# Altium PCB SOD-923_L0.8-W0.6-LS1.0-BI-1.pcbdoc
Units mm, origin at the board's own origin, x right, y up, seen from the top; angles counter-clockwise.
Board outline 14.1 x 13.46 mm, 2 copper layers (Top Layer, Bottom Layer), stack 0 mm thick; 1 components, 0 nets, 2 pads, 0 vias.
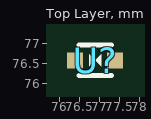
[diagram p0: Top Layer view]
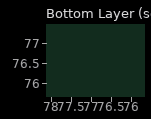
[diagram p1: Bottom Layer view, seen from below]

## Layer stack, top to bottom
Top Layer: signal copper (thickness not stored)
Bottom Layer: signal copper (thickness not stored)

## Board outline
83.95,69.85 69.85,69.85 69.85,83.312 83.95,83.312

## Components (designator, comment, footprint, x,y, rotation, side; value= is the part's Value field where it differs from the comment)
U? "" SOD-923_L0.8-W0.6-LS1.0-BI-1 76.9,76.581 r0 top

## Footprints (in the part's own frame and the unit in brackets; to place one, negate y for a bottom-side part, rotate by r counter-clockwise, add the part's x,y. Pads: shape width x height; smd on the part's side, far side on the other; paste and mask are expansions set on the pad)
SOD-923_L0.8-W0.6-LS1.0-BI-1 [mm]
  rect 0.4x0.4 smd: 1(-0.5,0) 2(0.5,0)
  silkscreen extent -0.41,-0.38 0.41,0.38

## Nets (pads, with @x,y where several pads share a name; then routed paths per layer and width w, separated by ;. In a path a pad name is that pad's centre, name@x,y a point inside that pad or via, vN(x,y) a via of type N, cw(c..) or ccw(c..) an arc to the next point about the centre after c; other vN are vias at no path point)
pads on no net: U?.1 U?.2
